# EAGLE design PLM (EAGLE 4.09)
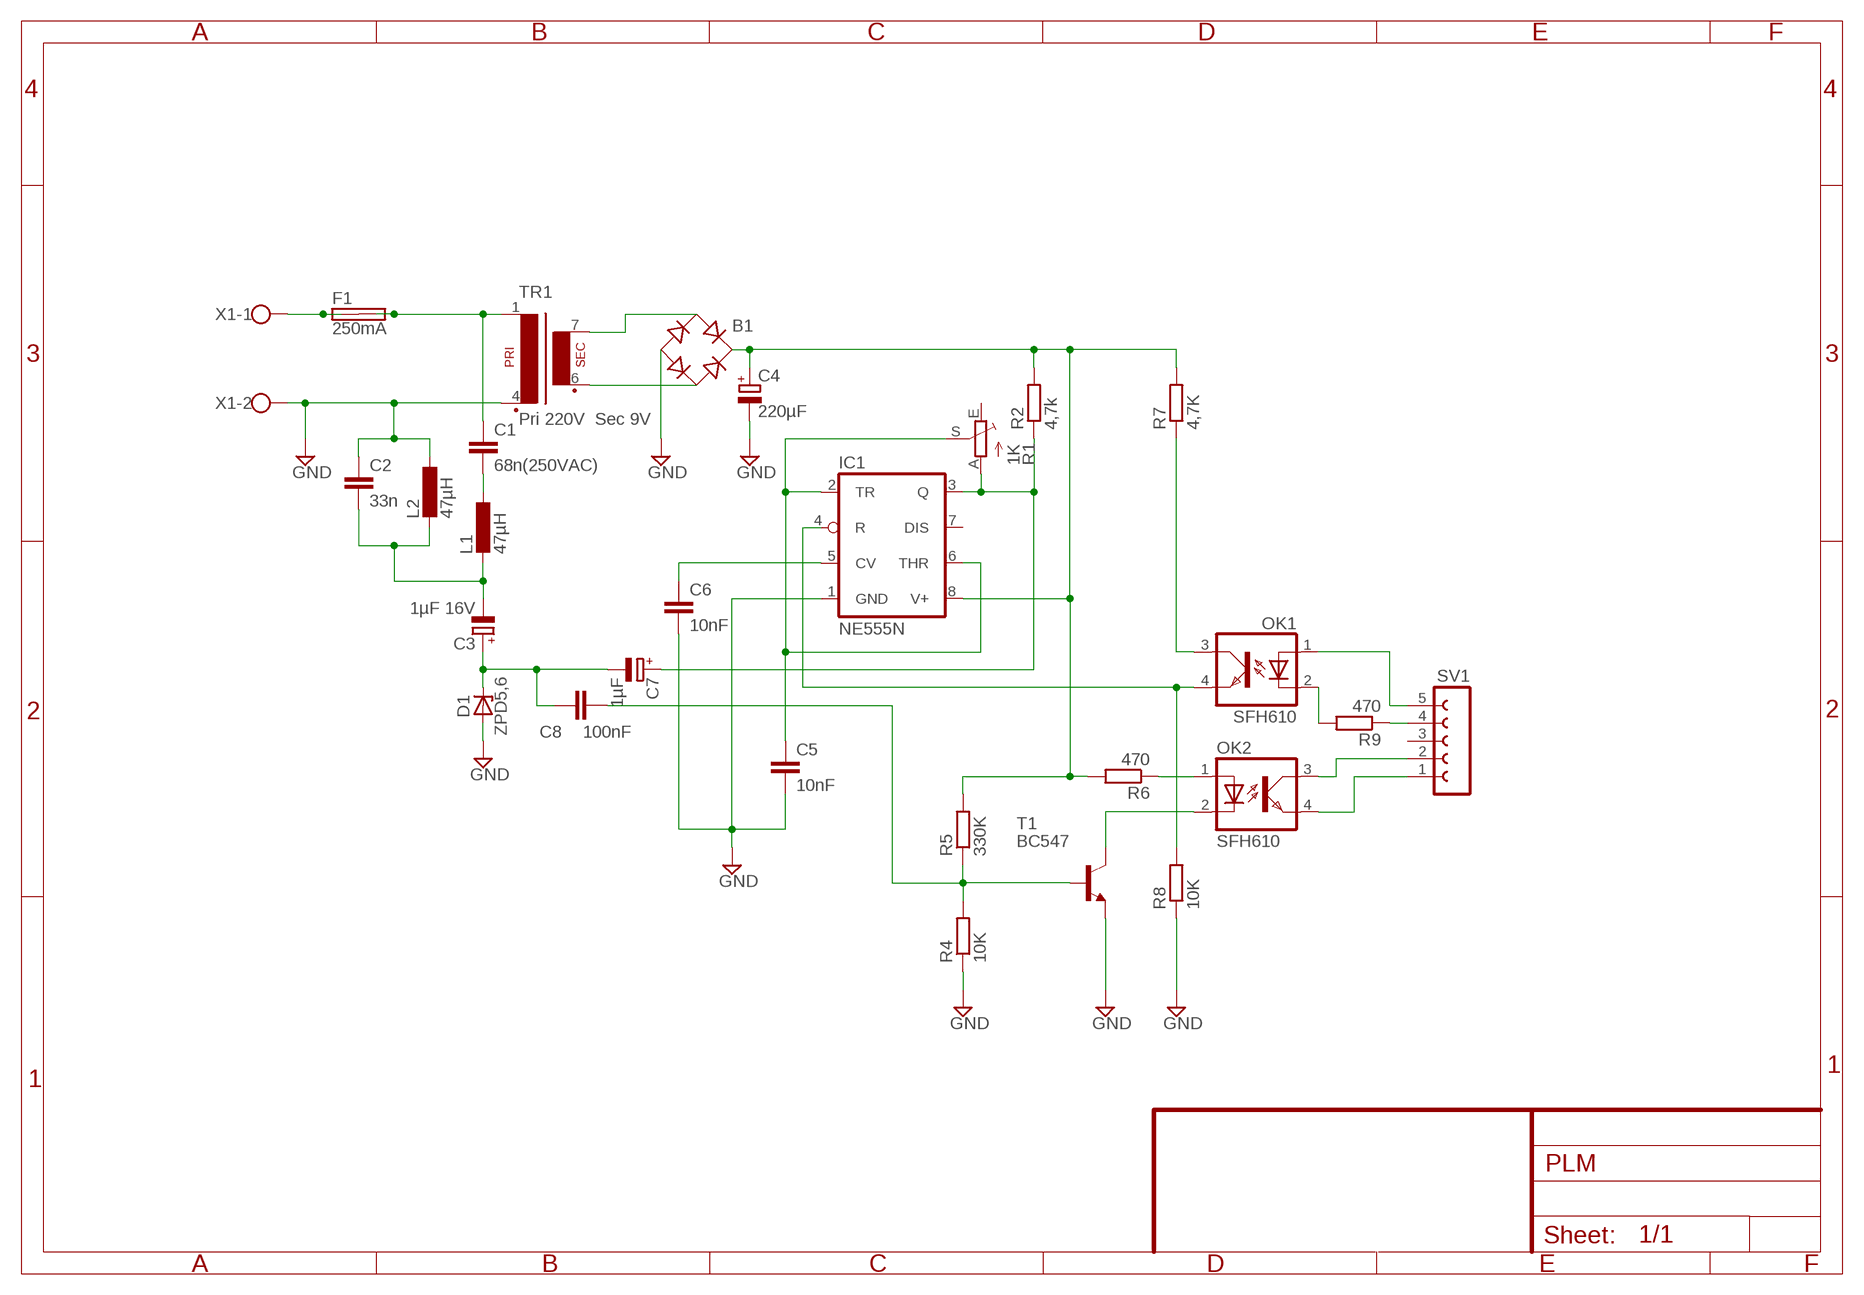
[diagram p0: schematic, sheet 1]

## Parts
B1  B-DIL  [B-DIL]
C1  68n(250VAC)  C-EU150-072X183  [C150-072X183]
C2  33n  C-EUC1206  [C1206]
C3  1µF 16V  CPOL-EUE2.5-5  [E2,5-5]
C4  220µF  CPOL-EUE3.5-10  [E3,5-10]
C5  10nF  C-EUC1206  [C1206]
C6  10nF  C-EUC1206  [C1206]
C7  1µF  CPOL-EUE2.5-5  [E2,5-5]
C8  100nF  C-EUC1206  [C1206]
D1  ZPD5,6  ZPD  [DO35Z10]
F1  250mA  SHK20L  [SHK20L]
IC1  NE555N  [DIL08]
L1  47µH  L-EU0204/5  [0204/5]
L2  47µH  L-EU0204/5  [0204/5]
OK1  SFH610  [DIL04]
OK2  SFH610  [DIL04]
R1  1K  TRIM_EU-B25P  [B25P]
R2  4,7k  R-EU_0207/10  [0207/10]
R4  10K  R-EU_0207/10  [0207/10]
R5  330K  R-EU_0207/10  [0207/10]
R6  470  R-EU_0207/10  [0207/10]
R7  4,7K  R-EU_M1206  [M1206]
R8  10K  R-EU_R1206  [R1206]
R9  470  R-EU_R1206  [R1206]
SV1  FE05-1  [FE05-1]
T1  BC547  [TO92]
TR1  Pri 220V Sec 9V  EE20-1  [EE20-1]
X1  W237-102  [W237-102]

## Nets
GND: B1.- C2.1 C4.- C5.2 C6.2 D1.A IC1.1(GND) L2.1 R4.1 R8.1 T1.1(E) TR1.4 X1.2
N$1: F1.1A F1.1B X1.1
N$2: C1.1 F1.2A F1.2B TR1.1
N$3: C3.+ C7.- C8.1 D1.C
N$8: B1.AC1 TR1.7
N$9: B1.AC2 TR1.6
N$10: C7.+ IC1.3(Q) R1.A R2.1
N$11: OK2.3(COL) SV1.2
N$12: C2.2 C3.- L1.2 L2.2
N$13: C1.2 L1.1
N$14: OK2.1(A) R6.1
N$15: OK2.2(C) T1.3(C)
N$16: C6.1 IC1.5(CV)
N$17: OK2.4(EMIT) SV1.1
N$18: R9.1 SV1.4
N$19: OK1.1(A) SV1.5
N$21: C8.2 R4.2 R5.1 T1.2(B)
N$22: C5.1 IC1.2(TR) IC1.6(THR) R1.S
N$23: OK1.2(C) R9.2
N$24: IC1.4(R) OK1.4(EMIT) R8.2
N$25: OK1.3(COL) R7.1
N$26: B1.+ C4.+ IC1.8(V+) R2.2 R5.2 R6.2 R7.2
Unconnected: IC1.7(DIS) R1.E SV1.3

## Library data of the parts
B1 = rectifier:B-DIL: RECTIFIER
C1 C2 C5 C6 C8 = rcl:C-EU: CAPACITOR, European symbol
C3 C4 C7 = rcl:CPOL-EU: POLARIZED CAPACITOR, European symbol
D1 = diode:ZPD: Z DIODE
F1 = fuse:SHK20L: FUSE HOLDER 5 x 20 mm, SH contact, SHH1 Schukat, E1073 Buerklin
IC1 = linear:*555: TIMER
L1 L2 = rcl:L-EU: INDUCTOR, European symbol
OK1 OK2 = optocoupler:SFH610: SIEMENS OPTO COUPLER
R1 = pot:TRIM_EU-: POTENTIOMETER
R2 R4-R9 = rcl:R-EU_: RESISTOR, European symbol
SV1 = con-lsta:FE05-1: FEMALE HEADER
T1 = transistor-npn:BC547: NPN TRANSISTOR
TR1 = trafo:EE20-1: TRANSFORMER 1 primary winding, 1 secondary winding ERA
X1 = con-wago-500:W237-102: WAGO SCREW CLAMP

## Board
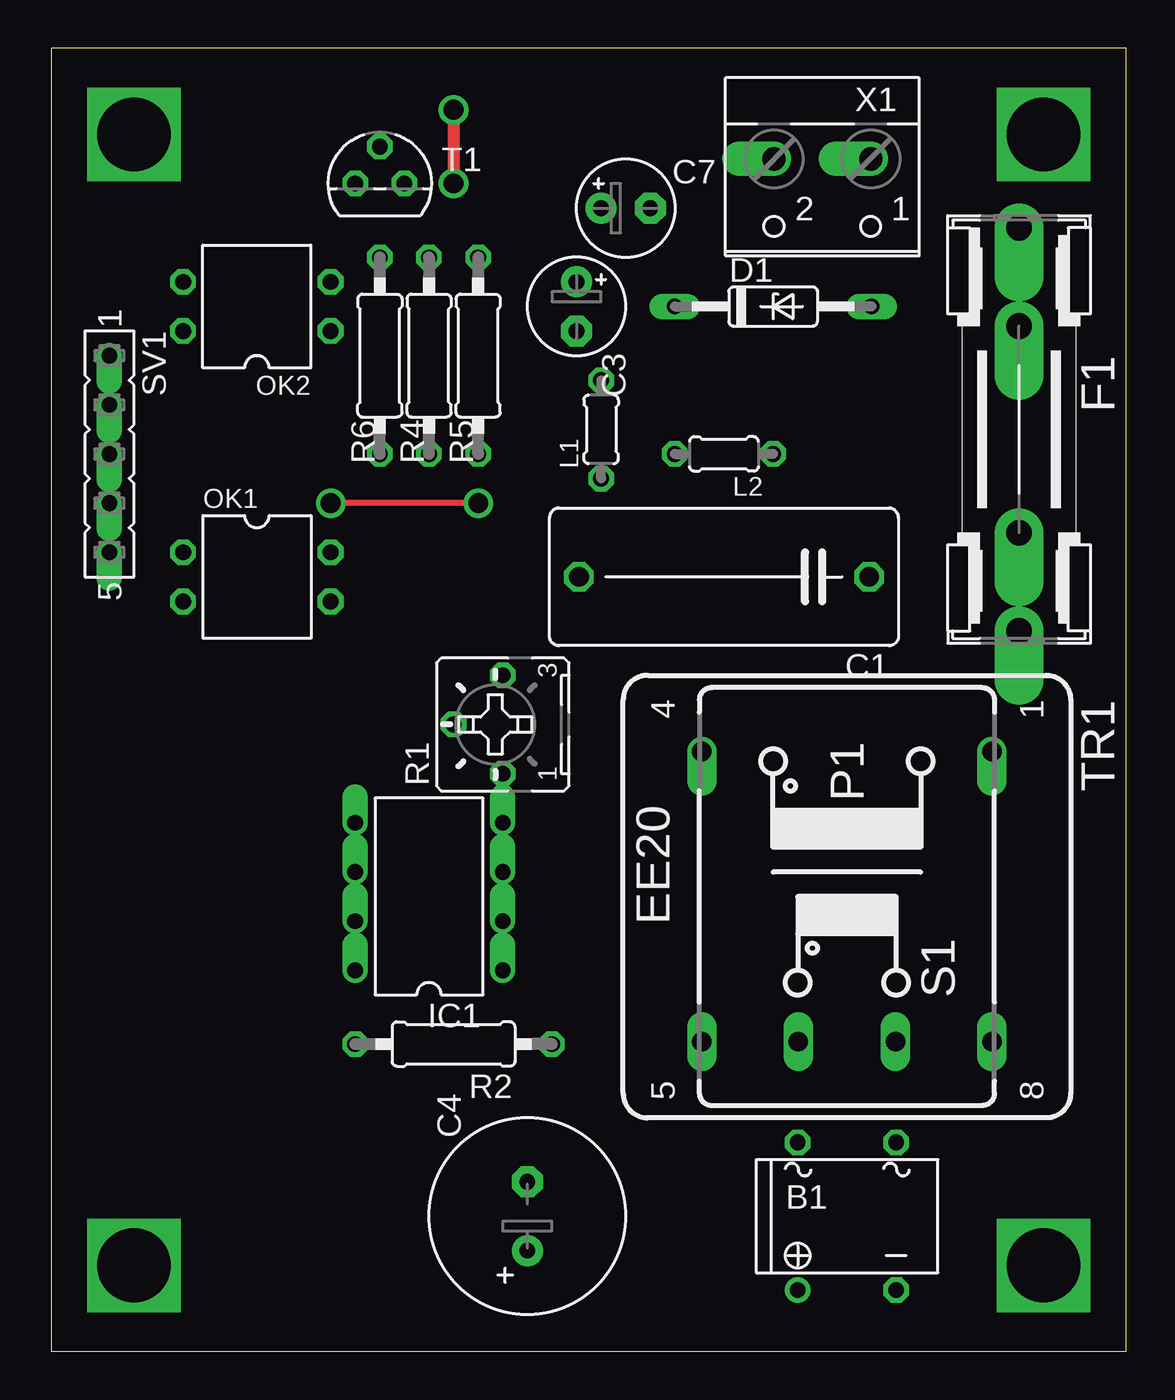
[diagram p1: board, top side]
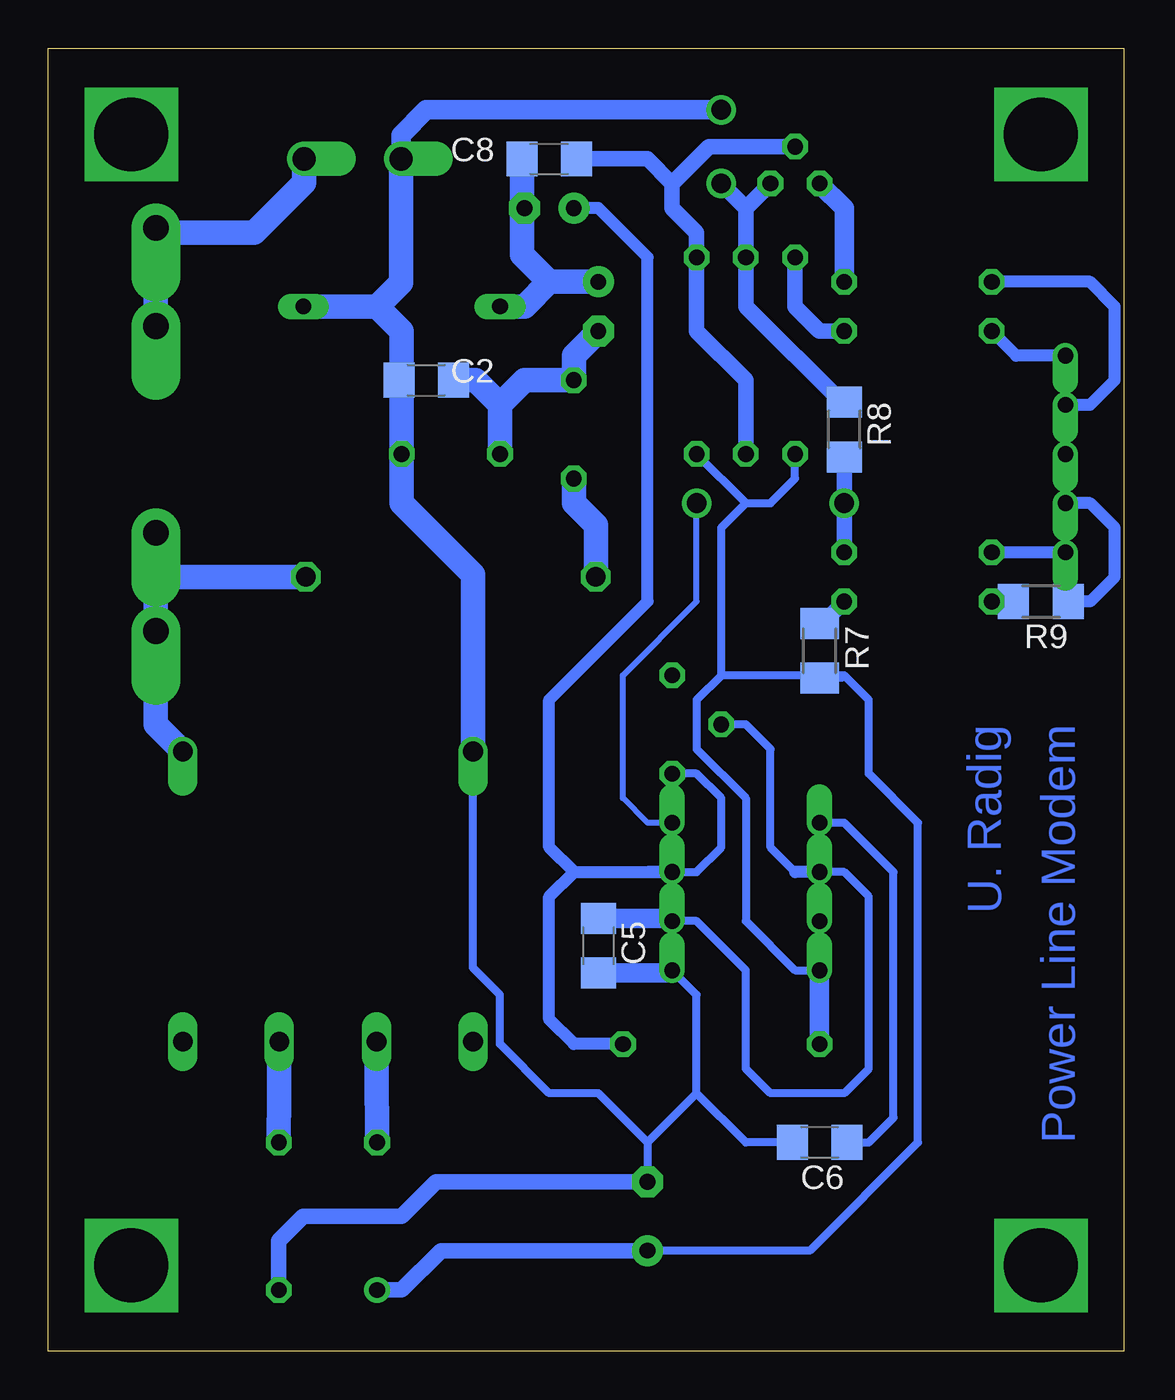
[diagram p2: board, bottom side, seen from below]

Size 55.55 x 67.29 mm. Coordinates in mm from the lower left corner, seen from the top.
Outline: 0,67.29 0,0 55.55,0 55.55,67.29 0,67.29
Copper layers used: Top, Bottom

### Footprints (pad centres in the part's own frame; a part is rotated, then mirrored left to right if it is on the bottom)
B-DIL = drill 0.813 round: + -2.54,-3.81 | drill 0.813 octagon: - 2.54,-3.81; AC1 2.54,3.81; AC2 -2.54,3.81
C150-072X183 = drill 1.016 octagon: 1 -7.493,0; 2 7.493,0
C1206 = smd 1.6 x 1.8: 1 -1.4,0; 2 1.4,0
E2,5-5 = drill 0.813 pad 1.6 round: + -1.27,0 | drill 0.813 pad 1.6 octagon: - 1.27,0
E3,5-10 = drill 0.813 pad 1.6 round: + -1.778,0 | drill 0.813 pad 1.6 octagon: - 1.778,0
DO35Z10 = drill 0.813 long: A 5.08,0; C -5.08,0
SHK20L = drill 1.321 pad 2.54 offset: 1A -10.414,0; 1B -5.334,0; 2A 10.414,0; 2B 5.334,0
DIL08 = drill 0.813 offset: 1 -3.81,-3.81; 2 -1.27,-3.81; 3 1.27,-3.81; 4 3.81,-3.81; 5 3.81,3.81; 6 1.27,3.81; 7 -1.27,3.81; 8 -3.81,3.81
0204/5 = drill 0.813 octagon: 1 -2.54,0; 2 2.54,0
DIL04 = drill 0.813 octagon: 1 -1.27,-3.81; 2 1.27,-3.81; 3 1.27,3.81; 4 -1.27,3.81
B25P = drill 0.813 octagon: A -2.54,0; E 2.54,0; S 0,2.54
0207/10 = drill 0.813 octagon: 1 -5.08,0; 2 5.08,0
M1206 = smd 1.6 x 2: 1 -1.4,0; 2 1.4,0
R1206 = smd 1.6 x 1.803: 1 -1.422,0; 2 1.422,0
FE05-1 = drill 0.813 offset: 1 -5.08,0; 2 -2.54,0; 3 0,0; 4 2.54,0; 5 5.08,0
TO92 = drill 0.813 octagon: 1 1.27,0; 2 0,1.905; 3 -1.27,0
EE20-1 = drill 1.016 offset: 1 -7.493,7.493; 4 -7.493,-7.493 | drill 1.016 long: 5 7.493,-7.493; 6 7.493,-2.515; 7 7.493,2.515; 8 7.493,7.493
W237-102 = drill 1.194 offset: 1 -2.5,-1.27; 2 2.5,-1.27

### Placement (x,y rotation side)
B1  41.11,6.97 0 top
C1  34.76,39.99 180 top
C2  36.03,50.15 0 bottom
C3  27.14,53.96 270 top
C4  24.6,6.97 90 top
C5  27.14,20.94 270 bottom
C6  15.71,10.78 180 bottom
C7  29.68,59.04 0 top
C8  29.68,61.58 0 bottom
D1  37.3,53.96 0 top
F1  50,47.61 270 top
IC1  19.52,23.48 90 top
L1  28.41,47.61 90 top
L2  34.76,46.34 180 top
OK1  10.63,39.99 270 top
OK2  10.63,53.96 90 top
R1  23.33,32.37 90 top
R2  20.79,15.86 180 top
R4  19.52,51.42 270 top
R5  22.06,51.42 270 top
R6  16.98,51.42 270 top
R7  15.71,36.18 270 bottom
R8  14.44,47.61 270 bottom
R9  4.28,38.72 180 bottom
SV1  3.01,46.34 270 top
T1  16.98,60.31 0 top
TR1  41.11,23.48 270 top
X1  39.84,60.31 180 top

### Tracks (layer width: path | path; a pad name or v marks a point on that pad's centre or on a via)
GND  (via drill 1.02)
  Top 0.61: v20.79,64.12 v20.79,60.31
  Bottom 0.305: 33.62,40.12 33.49,39.99 33.49,36.18
  Bottom 0.406: 22.06,13.32 19.52,10.78 C6.2 16.98,10.78 | 22.06,13.32 22.06,18.4 IC1.1 23.46,19.54 | 22.06,13.32 24.6,10.78 | 24.6,9.51 C4.- 24.6,10.78 | TR1.4 33.62,19.8 32.22,18.4 32.22,15.86 29.68,13.32 27.14,13.32 24.6,10.78
  Bottom 0.813: 19.52,59.04 R4.1 19.52,53.96 14.44,48.88 R8.1 | B1.- 43.65,5.7 42.38,6.97 37.3,6.97 35.52,8.75 C4.- | 19.52,59.04 T1.1 | v20.79,60.31 19.52,59.04
  Bottom 1.016: 23.46,19.54 C5.2 | v20.79,64.12 36.03,64.12 37.34,62.81 X1.2
  Bottom 1.27: X1.2 37.34,55.19 38.57,53.96 | 38.57,53.96 37.3,52.69 37.3,50.15 | 37.3,50.15 C2.1 | 38.57,53.96 D1.A | 37.3,50.15 L2.1 37.3,43.8 33.62,40.12 TR1.4
N$1
  Bottom 1.27: 50,52.69 F1.1B 50,57.77 | 50,57.77 F1.1A | X1.1 42.34,60.35 44.92,57.77 50,57.77
N$2
  Bottom 1.27: C1.1 50,39.99 F1.2B F1.2A 50,32.37 TR1.1
N$3
  Bottom 0.61: 31.08,59.17 C7.- 31.08,58.91
  Bottom 1.27: D1.C 30.95,53.96 29.68,55.23 | C3.+ 29.68,55.23 | 31.08,59.17 C8.1 | 29.68,55.23 31.08,56.63 31.08,58.91
N$4  (via drill 3.81)
  other vias: 51.27,62.85
N$5  (via drill 3.81)
  other vias: 51.27,4.43
N$6  (via drill 3.81)
  other vias: 4.28,4.43
N$7  (via drill 3.81)
  other vias: 4.28,62.85
N$8
  Bottom 1.27: TR1.7 43.62,13.34 B1.AC1
N$9
  Bottom 1.27: TR1.6 38.6,13.29 38.57,12.05 B1.AC2
N$10
  Bottom 0.406: IC1.3 22.06,24.75 20.79,26.02 20.79,28.56 22.06,29.83 R1.A
  Bottom 0.61: C7.+ 27.14,59.04 24.6,56.5 24.6,38.72 29.68,33.64 29.68,26.02 28.41,24.75 | 28.41,24.75 29.68,23.48 29.68,17.13 28.41,15.86 R2.1 | 24.6,24.75 IC1.3 28.41,24.75
N$11
  Bottom 0.61: SV1.2 1.74,48.88 0.47,50.15 0.47,53.96 1.74,55.23 OK2.3
N$12
  Bottom 0.406: C2.2 34.76,50.15
  Bottom 1.27: C3.- 28.41,51.42 L1.2 30.95,50.15 32.22,48.88 | 32.22,48.88 33.49,50.15 C2.2 | 32.22,48.88 L2.2
N$13
  Bottom 1.27: C1.2 27.27,42.66 28.41,43.8 L1.1
N$14
  Bottom 0.813: R6.1 16.98,53.96 15.71,52.69 OK2.1
N$15
  Bottom 1.016: OK2.2 14.44,59.04 T1.3
N$16
  Bottom 0.406: IC1.5 14.44,27.29 11.9,24.75 11.9,12.05 13.17,10.78 C6.1 14.44,10.78
N$17
  Bottom 0.61: SV1.1 5.55,51.42 OK2.4
N$18
  Bottom 0.305: R9.1 1.74,38.72
  Bottom 0.61: SV1.4 1.74,43.8 0.47,42.53 0.47,39.99 1.74,38.72 3.01,38.72
N$19
  Bottom 0.61: SV1.5 OK1.1
N$21
  Bottom 0.813: R4.2 19.52,50.15 22.06,52.69 R5.1 22.06,57.77 23.33,59.04 23.33,60.31 | T1.2 21.43,62.22 23.33,60.31 | 23.33,60.31 24.6,61.58 C8.2
N$22
  Bottom 0.406: 16.98,24.75 18.25,26.02 18.25,31.1 19.52,32.37 R1.S | 23.46,22.34 IC1.2 22.06,22.21 19.52,19.67 19.52,14.59 18.25,13.32 14.44,13.32 13.17,14.59 13.17,23.48 14.44,24.75 IC1.6
  Bottom 0.61: IC1.6 16.98,24.75
  Bottom 1.016: 23.46,22.34 C5.1
N$23
  Bottom 0.61: R9.2 OK1.2
N$24  (via drill 1.02)
  Top 0.305: v22.06,43.8 v14.44,43.8
  Bottom 0.305: IC1.4 24.6,27.29 25.87,28.56 25.87,34.91 22.06,38.72 v22.06,43.8
  Bottom 0.406: v14.44,43.8 R8.2
  Bottom 0.61: v14.44,43.8 14.44,46.34
  Bottom 0.813: OK1.4 v14.44,43.8 R8.2
N$25
  Bottom 0.406: R7.1 15.71,37.45
  Bottom 0.813: 15.71,37.45 OK1.3
N$26
  Bottom 0.406: R6.2 16.98,45.07 18.25,43.8 19.52,43.8 | 19.52,43.8 R5.2 | IC1.8 16.98,19.67 19.52,22.21 19.52,28.56 22.06,31.1 22.06,33.64 20.79,34.91 | 14.44,34.91 20.79,34.91 | 14.44,34.91 13.17,33.64 13.17,29.83 10.63,27.29 10.63,10.78 16.22,5.19 C4.+ | R7.2 14.57,34.78 14.44,34.91 | 19.52,43.8 20.79,42.53 20.79,34.91
  Bottom 0.813: C4.+ 35.27,5.19 37.3,3.16 B1.+
  Bottom 1.016: IC1.8 R2.2

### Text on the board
Bottom: Power Line Modem | U. Radig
